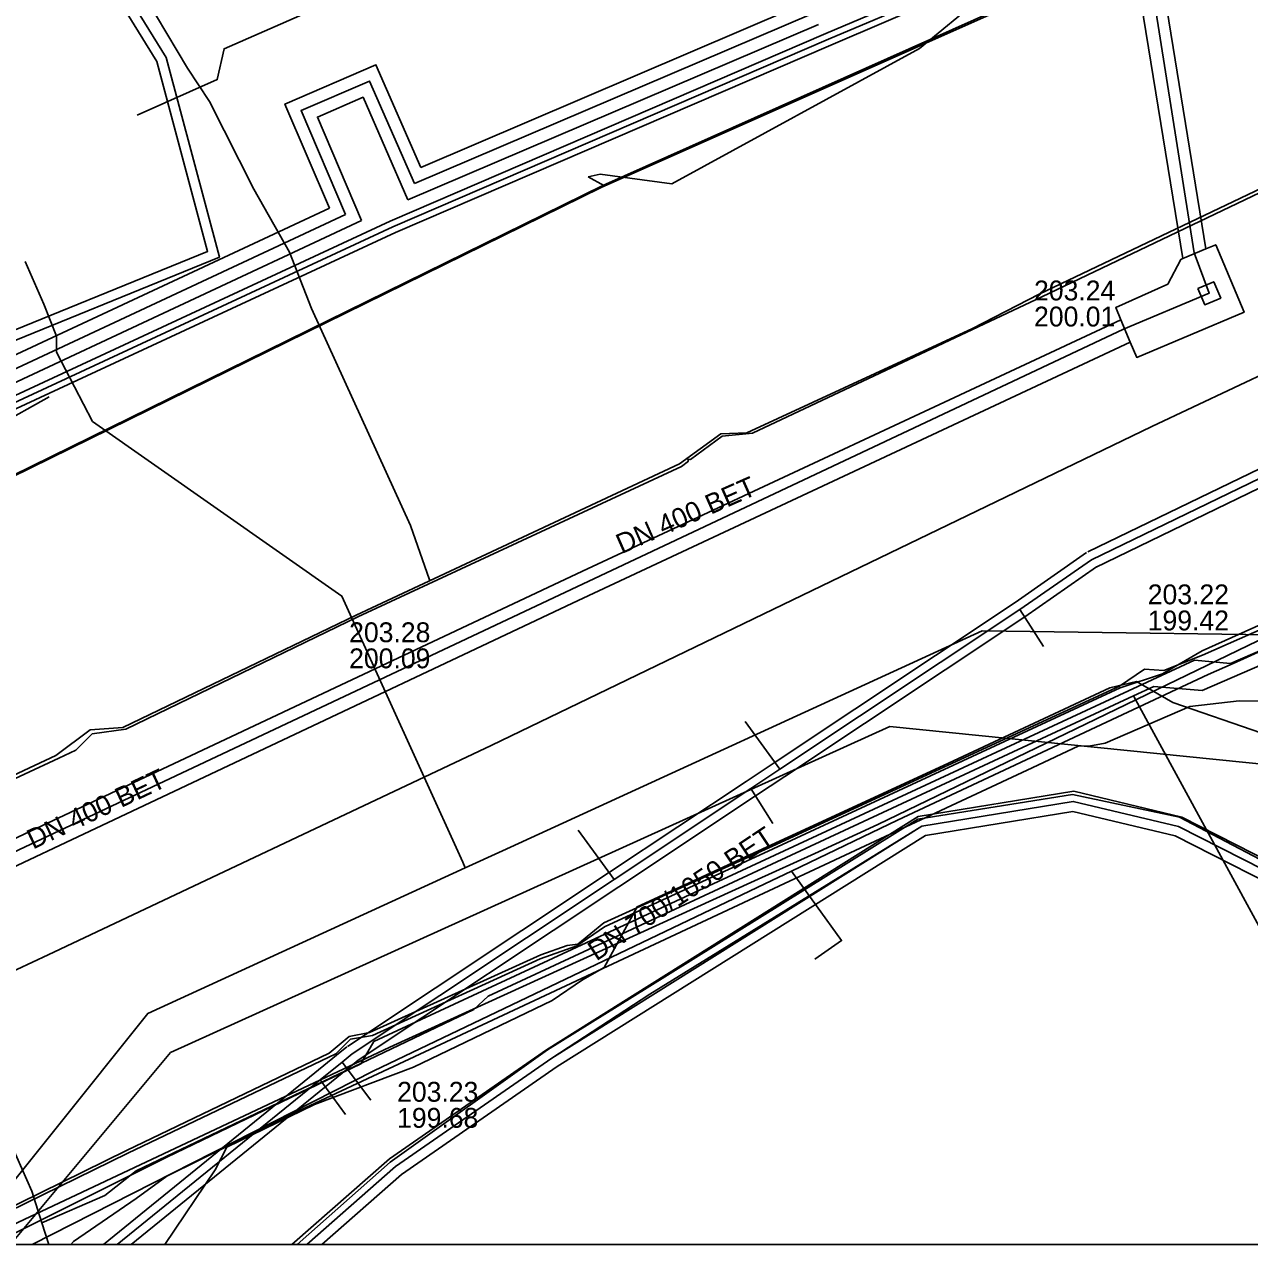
# Model space of a CAD drawing. Extents: x -600309 to -598967, y -1161267 to -1160292.
# Drawn here: x -599377.05 to -599327.71, y -1161267.03 to -1161217.9 of the extents above; entities that cross this region are included whole.
import ezdxf

# ---------------------------------------------------------------- set-up
doc = ezdxf.new("R2010")
doc.units = 0
for name, color, linetype in [('Vrstva 10', 7, 'Continuous'), ('Vrstva 12', 7, 'Continuous'), ('Vrstva 13', 7, 'Continuous'), ('Vrstva 19', 7, 'Continuous'), ('Vrstva 29', 7, 'Continuous'), ('Vrstva 30', 7, 'Continuous'), ('Vrstva 42', 7, 'Continuous'), ('Vrstva 44', 7, 'Continuous'), ('Vrstva 52', 7, 'Continuous'), ('Vrstva 55', 7, 'Continuous'), ('Vrstva 58', 7, 'Continuous'), ('Vrstva 63', 7, 'Continuous'), ('Vrstva 9', 7, 'Continuous')]:
    doc.layers.add(name, color=color, linetype=linetype)

msp = doc.modelspace()

# ---------------------------------------------------------------- linework, layer by layer
at = {"layer": 'Vrstva 10'}
for points in [[(-599336.05, -1161192.64), (-599330.39, -1161227.32)], [(-599335, -1161192.84), (-599329.47, -1161226.94)], [(-599334.222, -1161239.139), (-599323.199, -1161233.802), (-599303.673, -1161224.045)], [(-599303.361, -1161224.671), (-599322.89, -1161234.431), (-599333.916, -1161239.769)], [(-599332.51, -1161230.69), (-599332.25, -1161231.31), (-599327.93, -1161229.49), (-599329.07, -1161226.77), (-599329.47, -1161226.94)], [(-599330.39, -1161227.32), (-599329.47, -1161226.94)], [(-599332.89, -1161229.79), (-599333.1, -1161229.3), (-599331, -1161228.36), (-599330.48, -1161227.36), (-599330.39, -1161227.32)], [(-599329.79, -1161228.53), (-599329.15, -1161228.26), (-599328.87, -1161228.92), (-599329.51, -1161229.19), (-599329.79, -1161228.53)], [(-599383.8, -1161253.67), (-599354.58, -1161239.92), (-599332.89, -1161229.79)], [(-599332.89, -1161229.79), (-599332.51, -1161230.69)], [(-599332.51, -1161230.69), (-599354.75, -1161241.1), (-599383.42, -1161254.63)], [(-599364.044, -1161259.059), (-599353.494, -1161252.043), (-599347.989, -1161248.383), (-599346.815, -1161247.602), (-599337.151, -1161241.175), (-599334.269, -1161239.167)], [(-599333.869, -1161239.741), (-599336.757, -1161241.754), (-599346.428, -1161248.185), (-599347.602, -1161248.966), (-599353.106, -1161252.626), (-599363.656, -1161259.641)], [(-599373.87, -1161267.031), (-599365.36, -1161260.125), (-599364.483, -1161259.413), (-599364.071, -1161259.078)], [(-599363.629, -1161259.622), (-599364.041, -1161259.956), (-599372.759, -1161267.031)]]:
    msp.add_lwpolyline(points, dxfattribs=at)
at = {"layer": 'Vrstva 12'}
for p, q in [((-599320.364, -1161267.031), (-599332.38, -1161244.94)), ((-599376.07, -1161267.031), (-599376.35, -1161266.16))]:
    msp.add_line(p, q, dxfattribs=at)
for points in [[(-599385.6, -1161254.99), (-599383.62, -1161254.12), (-599332.78, -1161230.17), (-599329.33, -1161228.72), (-599329.94, -1161227.1), (-599335.37, -1161192.76), (-599335.01, -1161190.85)], [(-599324.07, -1161241.12), (-599329.01, -1161243.51), (-599334.7, -1161246.26)], [(-599375.184, -1161267.031), (-599375.08, -1161266.91), (-599372.56, -1161265.18), (-599371.32, -1161264.28), (-599365.97, -1161261.63), (-599347.87, -1161253.16), (-599336.47, -1161247.83), (-599334.59, -1161246.95), (-599334.18, -1161246.96), (-599333.52, -1161246.84), (-599330.11, -1161245.37), (-599328.13, -1161245.14), (-599322.96, -1161245.17), (-599321.9, -1161245.66), (-599320.58, -1161245.92), (-599319.14, -1161245.52), (-599311.67, -1161242), (-599310.27, -1161241.48), (-599308.76, -1161241.57), (-599306.87, -1161242.86), (-599305.26, -1161244.79)], [(-599343.29, -1161250.61), (-599341.89, -1161249.94), (-599329.38, -1161244.08), (-599328.37, -1161243.63), (-599324.96, -1161242.09), (-599324.27, -1161241.78)], [(-599331.56, -1161244.56), (-599329.62, -1161244.72), (-599324.28, -1161242.41), (-599322.82, -1161242.12), (-599321.2, -1161243.06), (-599319.27, -1161244.73), (-599318.64, -1161245.79), (-599313.82, -1161243.47)], [(-599332.38, -1161244.94), (-599331.56, -1161244.56)], [(-599376.35, -1161266.16), (-599373.82, -1161265.06), (-599372.56, -1161264.07), (-599358.95, -1161257.57), (-599358.37, -1161257.03), (-599356.47, -1161256.15), (-599332.38, -1161244.94)], [(-599334.7, -1161246.26), (-599342.68, -1161250.12), (-599345.22, -1161251.28)], [(-599346.16, -1161252), (-599343.29, -1161250.61)], [(-599345.22, -1161251.28), (-599347.65, -1161252.39)], [(-599346.16, -1161252), (-599347.23, -1161252.51), (-599362.98, -1161260.04), (-599376.747, -1161267.031)], [(-599345.22, -1161255.54), (-599344.14, -1161254.79), (-599346.16, -1161252)], [(-599347.65, -1161252.39), (-599362.34, -1161259.09), (-599378.25, -1161266.58)], [(-599376.35, -1161266.16), (-599376.75, -1161264.89), (-599381.4, -1161254.38), (-599381.66, -1161253.94), (-599382.51, -1161253.52), (-599385.33, -1161254.87), (-599385.6, -1161254.99)]]:
    msp.add_lwpolyline(points, dxfattribs=at)
at = {"layer": 'Vrstva 13'}
for points in [[(-599359.297, -1161251.863), (-599359.399, -1161251.64), (-599364.266, -1161240.919), (-599374.308, -1161233.888), (-599375.76, -1161231.1), (-599375.76, -1161230.457), (-599376.276, -1161229.158), (-599377.023, -1161227.451)], [(-599379.539, -1161267.031), (-599372.088, -1161257.728), (-599359.297, -1161251.863), (-599357.798, -1161251.176), (-599338.48, -1161242.32), (-599323.02, -1161242.54), (-599316.251, -1161239.468), (-599311.113, -1161237.136), (-599310.694, -1161236.973), (-599310.172, -1161236.769)]]:
    msp.add_lwpolyline(points, dxfattribs=at)
at = {"layer": 'Vrstva 19'}
for points in [[(-599343.44, -1161208.8), (-599343.53, -1161208.74), (-599343.57, -1161208.68), (-599351.87, -1161211.65), (-599358.06, -1161214.08), (-599369.01, -1161218.88), (-599369.29, -1161220.12), (-599372.511, -1161221.552)], [(-599377.61, -1161267.031), (-599371.17, -1161259.3), (-599342.2, -1161246.17), (-599321.88, -1161248.22), (-599321.1, -1161247.94), (-599312.06, -1161243.57), (-599310.71, -1161237.93)]]:
    msp.add_lwpolyline(points, dxfattribs=at)
at = {"layer": 'Vrstva 29'}
for p, q in [((-599344.672, -1161218.498), (-599329.268, -1161211.913)), ((-599345.272, -1161217.442), (-599361.346, -1161224.309)), ((-599364.121, -1161225.549), (-599432.27, -1161257.371))]:
    msp.add_line(p, q, dxfattribs=at)
for points in [[(-599379.591, -1161234.12), (-599362.215, -1161226.054), (-599344.672, -1161218.498)], [(-599361.346, -1161224.309), (-599363.155, -1161220.178), (-599365.909, -1161221.365), (-599364.121, -1161225.549)]]:
    msp.add_lwpolyline(points, dxfattribs=at)
at = {"layer": 'Vrstva 30'}
for p, q in [((-599344.77, -1161218.268), (-599329.14, -1161211.587)), ((-599329.396, -1161212.239), (-599344.573, -1161218.728)), ((-599345.958, -1161217.192), (-599361.087, -1161223.655)), ((-599345.076, -1161217.902), (-599361.605, -1161224.963)), ((-599364.771, -1161225.301), (-599432.028, -1161256.706)), ((-599363.471, -1161225.798), (-599432.512, -1161258.036))]:
    msp.add_line(p, q, dxfattribs=at)
for points in [[(-599379.922, -1161233.998), (-599362.317, -1161225.825), (-599344.771, -1161218.269)], [(-599344.573, -1161218.728), (-599362.113, -1161226.282), (-599379.26, -1161234.242)], [(-599361.087, -1161223.655), (-599362.896, -1161219.522), (-599366.565, -1161221.103), (-599364.771, -1161225.301)], [(-599361.605, -1161224.963), (-599363.414, -1161220.834), (-599365.253, -1161221.627), (-599363.471, -1161225.798)]]:
    msp.add_lwpolyline(points, dxfattribs=at)
at = {"layer": 'Vrstva 42'}
for p, q in [((-599328.47, -1161243.63), (-599324.73, -1161242.02)), ((-599362.98, -1161258.86), (-599329.93, -1161243.5)), ((-599329.93, -1161243.5), (-599328.47, -1161243.63)), ((-599363.5, -1161259.76), (-599362.98, -1161258.86)), ((-599371.32, -1161263.51), (-599363.5, -1161259.76)), ((-599378.359, -1161267.031), (-599371.32, -1161263.51))]:
    msp.add_line(p, q, dxfattribs=at)
for points in [[(-599354.35, -1161224.035), (-599353.87, -1161223.93), (-599350.98, -1161224.32), (-599350.984, -1161224.313), (-599341.004, -1161218.864), (-599338.515, -1161216.814), (-599325.587, -1161209.739), (-599325.092, -1161209.468), (-599325.196, -1161210.096), (-599325.279, -1161211.383), (-599325.054, -1161212.814), (-599323.019, -1161218.93), (-599321.517, -1161222.89), (-599318.96, -1161229.645), (-599317.747, -1161232.635), (-599316.216, -1161236.545), (-599315.956, -1161236.575), (-599315.252, -1161236.429), (-599307.447, -1161234.625), (-599302.834, -1161233.356), (-599298.522, -1161231.926), (-599293.176, -1161230.612), (-599287.233, -1161229.97), (-599281.039, -1161229.59)], [(-599354.35, -1161224.035), (-599353.87, -1161223.93), (-599350.98, -1161224.32), (-599350.984, -1161224.313), (-599341.004, -1161218.864), (-599338.515, -1161216.814), (-599325.587, -1161209.739), (-599325.092, -1161209.468), (-599325.196, -1161210.096), (-599325.279, -1161211.383), (-599325.054, -1161212.814), (-599323.019, -1161218.93), (-599321.517, -1161222.89), (-599318.96, -1161229.645), (-599317.747, -1161232.635), (-599316.216, -1161236.545), (-599315.956, -1161236.575), (-599315.252, -1161236.429), (-599307.447, -1161234.625), (-599302.834, -1161233.356), (-599298.522, -1161231.926), (-599293.176, -1161230.612), (-599287.233, -1161229.97), (-599281.039, -1161229.59)], [(-599354.35, -1161224.035), (-599353.87, -1161223.93), (-599350.98, -1161224.32), (-599350.984, -1161224.313), (-599341.004, -1161218.864), (-599338.515, -1161216.814), (-599325.587, -1161209.739), (-599325.092, -1161209.468), (-599325.196, -1161210.096), (-599325.279, -1161211.383), (-599325.054, -1161212.814), (-599323.019, -1161218.93), (-599321.517, -1161222.89), (-599318.96, -1161229.645), (-599317.747, -1161232.635), (-599316.216, -1161236.545), (-599315.956, -1161236.575), (-599315.252, -1161236.429), (-599307.447, -1161234.625), (-599302.834, -1161233.356), (-599298.522, -1161231.926), (-599293.176, -1161230.612), (-599287.233, -1161229.97), (-599281.039, -1161229.59)], [(-599374.389, -1161215.06), (-599371.718, -1161219.393), (-599369.676, -1161227.037), (-599379.315, -1161230.957), (-599380.09, -1161231.318), (-599380.133, -1161231.212), (-599380.318, -1161231.288), (-599380.504, -1161231.364), (-599380.495, -1161231.386), (-599380.302, -1161231.858), (-599380, -1161231.717), (-599379.155, -1161231.323), (-599369.198, -1161227.275), (-599371.346, -1161219.233), (-599374.031, -1161214.88)], [(-599354.35, -1161224.035), (-599353.87, -1161223.93), (-599350.98, -1161224.32), (-599350.984, -1161224.313), (-599341.004, -1161218.864), (-599338.515, -1161216.814)], [(-599354.35, -1161224.035), (-599353.87, -1161223.93), (-599350.98, -1161224.32), (-599350.984, -1161224.313), (-599341.004, -1161218.864), (-599338.515, -1161216.814)], [(-599353.72, -1161224.39), (-599354.35, -1161224.035)], [(-599366.285, -1161267.031), (-599362.354, -1161263.576), (-599356.031, -1161259.192), (-599341.054, -1161249.798), (-599334.791, -1161248.781), (-599330.431, -1161249.824), (-599325.398, -1161252.382), (-599323.489, -1161251.584), (-599320.383, -1161250.214), (-599310.158, -1161245.605), (-599303.826, -1161242.627), (-599300.88, -1161248.329), (-599301.993, -1161248.911)], [(-599302.165, -1161248.551), (-599301.412, -1161248.174), (-599303.992, -1161243.147), (-599309.988, -1161245.967), (-599320.227, -1161250.583), (-599323.331, -1161251.952), (-599325.414, -1161252.822), (-599330.57, -1161250.202), (-599334.806, -1161249.189), (-599340.91, -1161250.18), (-599355.811, -1161259.526), (-599362.107, -1161263.892), (-599365.678, -1161267.031)], [(-599365.072, -1161267.031), (-599361.86, -1161264.208), (-599355.591, -1161259.86), (-599340.766, -1161250.562), (-599334.821, -1161249.597), (-599330.709, -1161250.58), (-599325.43, -1161253.262), (-599323.173, -1161252.32), (-599320.071, -1161250.952), (-599309.818, -1161246.329), (-599304.158, -1161243.667), (-599301.931, -1161247.978), (-599302.338, -1161248.189)]]:
    msp.add_lwpolyline(points, dxfattribs=at)
at = {"layer": 'Vrstva 44'}
for points in [[(-599366.069, -1161267.031), (-599362.318, -1161263.719), (-599355.989, -1161259.196), (-599351.968, -1161256.69), (-599341.07, -1161249.897), (-599334.833, -1161248.911), (-599330.525, -1161249.82), (-599325.411, -1161252.505), (-599323.501, -1161251.68), (-599320.31, -1161250.214), (-599304.027, -1161242.527), (-599277.227, -1161230.875), (-599258.651, -1161232.996)], [(-599365.678, -1161267.031), (-599362.107, -1161263.892), (-599355.811, -1161259.526), (-599351.866, -1161256.957), (-599340.91, -1161250.18), (-599334.806, -1161249.189), (-599330.57, -1161250.202), (-599325.414, -1161252.822), (-599323.331, -1161251.952), (-599320.227, -1161250.583), (-599303.909, -1161242.887), (-599277.202, -1161231.07), (-599258.787, -1161233.207)]]:
    msp.add_lwpolyline(points, dxfattribs=at)
at = {"layer": 'Vrstva 52'}
msp.add_lwpolyline([(-599443.556, -1161267.031), (-599429.25, -1161260.28), (-599403.97, -1161248.61), (-599379.15, -1161236.86), (-599353.76, -1161224.39), (-599328.21, -1161212.98), (-599317.52, -1161181.99), (-599328.8, -1161153.56), (-599345.285, -1161119.772), (-599395.536, -1161081.384), (-599430.76, -1161091.53)], dxfattribs=at)
at = {"layer": 'Vrstva 55'}
for points in [[(-599417.457, -1161267.031), (-599414.1, -1161265.46), (-599400.09, -1161258.8), (-599400.02, -1161258.73), (-599399.52, -1161258.24), (-599398.06, -1161257.9), (-599386.75, -1161252.6), (-599375.67, -1161247.44), (-599374.98, -1161247.12), (-599374.32, -1161246.47), (-599372.97, -1161246.28), (-599363.62, -1161241.76), (-599350.59, -1161235.7), (-599350.31, -1161235.49), (-599350.33, -1161235.4), (-599350.22, -1161235.42), (-599348.95, -1161234.48), (-599347.73, -1161234.36), (-599336.07, -1161228.87), (-599324.87, -1161223.51), (-599324.82, -1161223.47), (-599321.69, -1161221.5), (-599317.03, -1161217.76)], [(-599324.56, -1161241.07), (-599329.6, -1161243.3), (-599331.16, -1161243.91), (-599331.94, -1161243.86), (-599332.95, -1161244.55), (-599346.92, -1161250.99), (-599353.72, -1161254.08), (-599354.76, -1161254.94), (-599355.19, -1161254.99), (-599356.26, -1161255.37), (-599363.15, -1161258.5), (-599363.97, -1161258.65), (-599364.78, -1161259.33), (-599372.94, -1161263.25), (-599379.86, -1161266.64)]]:
    msp.add_lwpolyline(points, dxfattribs=at)
at = {"layer": 'Vrstva 58'}
for points in [[(-599430.967, -1161091.647), (-599395.423, -1161081.797), (-599342.739, -1161124.011), (-599328.906, -1161153.63), (-599317.253, -1161182.504), (-599328.159, -1161213.041), (-599353.818, -1161224.464), (-599379.19, -1161236.921), (-599403.873, -1161248.573), (-599429.072, -1161260.169), (-599443.589, -1161267.031)], [(-599379.62, -1161203.83), (-599377.92, -1161204.85), (-599376.45, -1161207.19), (-599375.89, -1161208.97), (-599375.33, -1161211.08), (-599374.11, -1161213.28), (-599372.57, -1161216.16), (-599370.48, -1161219.66), (-599369.6, -1161221), (-599367.82, -1161224.53), (-599366.38, -1161227.07), (-599365.49, -1161229.34), (-599361.499, -1161238.071), (-599360.74, -1161240.26)], [(-599417.759, -1161267.031), (-599414.19, -1161265.36), (-599400.58, -1161258.91), (-599399.55, -1161258.13), (-599398.11, -1161257.8), (-599386.82, -1161252.51), (-599375.79, -1161247.34), (-599374.41, -1161246.31), (-599373.09, -1161246.21), (-599363.69, -1161241.69), (-599350.67, -1161235.6), (-599349.01, -1161234.38), (-599347.96, -1161234.35), (-599338.87, -1161230.14), (-599336.18, -1161228.76), (-599325.17, -1161223.51), (-599321.55, -1161221.63), (-599316.93, -1161217.89)], [(-599417.759, -1161267.031), (-599414.19, -1161265.36), (-599400.58, -1161258.91), (-599399.55, -1161258.13), (-599398.11, -1161257.8), (-599386.82, -1161252.51), (-599375.79, -1161247.34), (-599374.41, -1161246.31), (-599373.09, -1161246.21), (-599363.69, -1161241.69), (-599350.67, -1161235.6), (-599349.01, -1161234.38), (-599347.96, -1161234.35), (-599338.87, -1161230.14), (-599336.18, -1161228.76), (-599325.17, -1161223.51), (-599321.55, -1161221.63), (-599316.93, -1161217.89)], [(-599380.446, -1161267.031), (-599379.78, -1161266.72), (-599372.89, -1161263.35), (-599364.51, -1161259.36), (-599363.92, -1161258.76), (-599363.03, -1161258.62), (-599356.28, -1161255.53), (-599354.8, -1161255), (-599353.69, -1161254.24), (-599346.89, -1161251.1), (-599332.92, -1161244.62), (-599331.22, -1161244.05), (-599329.61, -1161243.12), (-599324.57, -1161240.86), (-599323.24, -1161240.45), (-599318.69, -1161238.22), (-599316.43, -1161237.56), (-599314.82, -1161236.89), (-599314.16, -1161236.13), (-599308.93, -1161233.75), (-599304.81, -1161232.21), (-599299.98, -1161230.54), (-599294.9, -1161229.07), (-599282.9, -1161228.13)], [(-599380.446, -1161267.031), (-599379.78, -1161266.72), (-599372.89, -1161263.35), (-599364.51, -1161259.36), (-599363.92, -1161258.76), (-599363.03, -1161258.62), (-599356.28, -1161255.53), (-599354.8, -1161255), (-599353.69, -1161254.24), (-599346.89, -1161251.1), (-599332.92, -1161244.62), (-599331.22, -1161244.05), (-599329.61, -1161243.12), (-599324.57, -1161240.86), (-599323.24, -1161240.45), (-599318.69, -1161238.22), (-599316.43, -1161237.56), (-599314.82, -1161236.89), (-599314.16, -1161236.13), (-599308.93, -1161233.75), (-599304.81, -1161232.21), (-599299.98, -1161230.54), (-599294.9, -1161229.07), (-599282.9, -1161228.13)], [(-599371.402, -1161267.031), (-599369.37, -1161264.02), (-599368.9, -1161263.11), (-599365.37, -1161261.39), (-599361.38, -1161259.89), (-599355.8, -1161257.2), (-599354.57, -1161256.37), (-599353.7, -1161255.88), (-599352.38, -1161253.44), (-599340.03, -1161247.74), (-599333.33, -1161244.61), (-599332.26, -1161244.36), (-599330.8, -1161245.21), (-599327.21, -1161246.44), (-599323.16, -1161245.72), (-599319.17, -1161246.25), (-599312.44, -1161243.03), (-599311.01, -1161242.36)]]:
    msp.add_lwpolyline(points, dxfattribs=at)
at = {"layer": 'Vrstva 63'}
msp.add_lwpolyline([(-600308.541, -1160292.347), (-598967.108, -1160292.347), (-598967.108, -1161267.031), (-600308.541, -1161267.031)], close=True, dxfattribs=at)
at = {"layer": 'Vrstva 9'}
for p, q in [((-599376.055, -1161232.9), (-599385.315, -1161238.02)), ((-599358.26, -1161246.938), (-599331.646, -1161234.094)), ((-599336.003, -1161242.944), (-599336.954, -1161241.465)), ((-599348.025, -1161245.974), (-599346.622, -1161247.893)), ((-599346.912, -1161250.074), (-599347.796, -1161248.674)), ((-599354.749, -1161250.342), (-599353.3, -1161252.334)), ((-599363.106, -1161261.214), (-599364.262, -1161259.684)), ((-599364.117, -1161261.797), (-599365.139, -1161260.397))]:
    msp.add_line(p, q, dxfattribs=at)
for points in [[(-599331.646, -1161234.094), (-599316.776, -1161227.083), (-599305.253, -1161221.649), (-599298.813, -1161218.613)], [(-599334.069, -1161239.454), (-599323.044, -1161234.116), (-599303.517, -1161224.358)], [(-599363.85, -1161259.35), (-599353.3, -1161252.334), (-599347.796, -1161248.674), (-599346.622, -1161247.893), (-599336.954, -1161241.465), (-599334.069, -1161239.454)], [(-599386.08, -1161260.05), (-599377.358, -1161255.96), (-599376.104, -1161255.368), (-599358.26, -1161246.938)], [(-599373.314, -1161267.031), (-599365.139, -1161260.397), (-599364.262, -1161259.684), (-599363.85, -1161259.35)]]:
    msp.add_lwpolyline(points, dxfattribs=at)

# ---------------------------------------------------------------- texts
at = {"layer": 'Vrstva 12'}
for s, p in [('203.24', (-599336.388, -1161229.013)), ('200.01', (-599336.388, -1161230.063)), ('203.22', (-599331.809, -1161241.251)), ('199.42', (-599331.809, -1161242.301)), ('203.28', (-599363.975, -1161242.777)), ('200.09', (-599363.975, -1161243.827)), ('203.23', (-599362.043, -1161261.282)), ('199.68', (-599362.043, -1161262.332))]:
    msp.add_text(s, height=0.8, dxfattribs=at).set_placement(p)
for s, rotation, p in [('DN 400 BET', 23.832, (-599353, -1161239.233)), ('DN 400 BET', 25.2674, (-599376.71, -1161251.132)), ('DN 700/1050 BET', 33.6326, (-599354.016, -1161255.636))]:
    msp.add_text(s, height=0.8, rotation=rotation, dxfattribs=at).set_placement(p)

doc.saveas('drawing.dxf')
